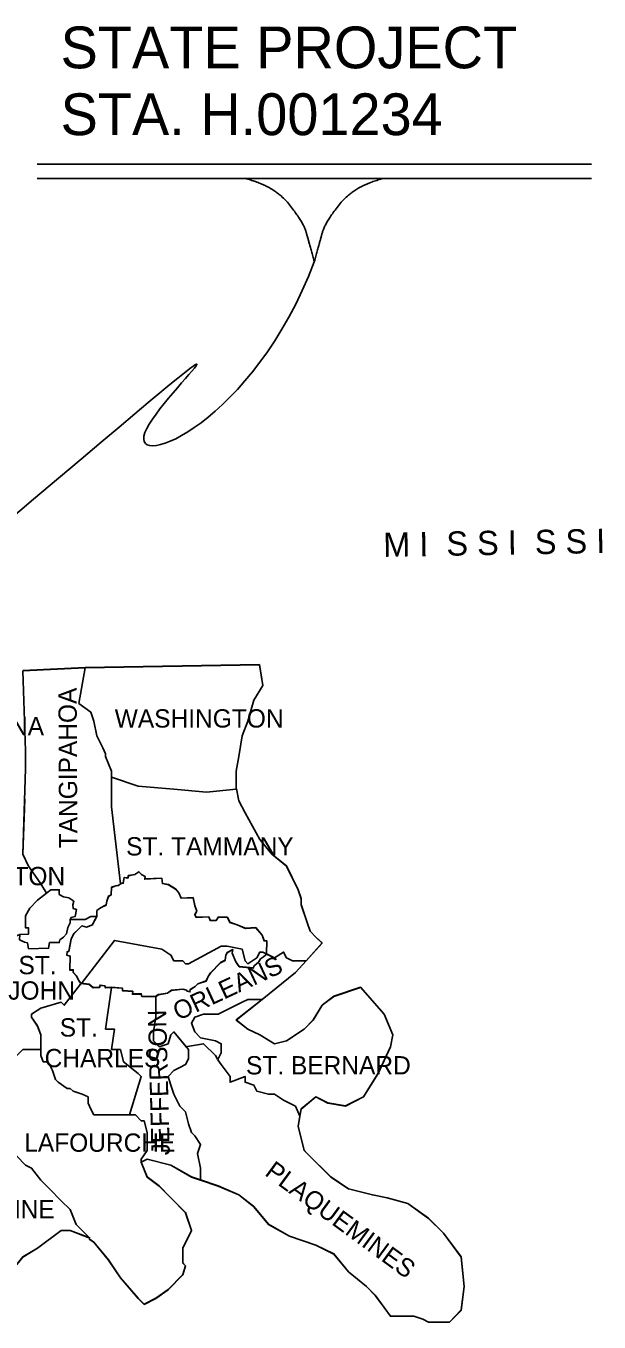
# Model space of a CAD drawing. Extents: x 0.23 to 2.82, y 0.04 to 1.79.
# Drawn here: x 2.468 to 2.6143, y 1.4148 to 1.7459 of the extents above; entities that cross this region are included whole.
import ezdxf

# ---------------------------------------------------------------- set-up
doc = ezdxf.new("R2010")
doc.units = 0
for name, color, linetype in [('Annotation', 7, 'Continuous'), ('Dist02', 7, 'Continuous'), ('Dist62', 7, 'Continuous'), ('Standard Info', 7, 'Continuous')]:
    doc.layers.add(name, color=color, linetype=linetype)

msp = doc.modelspace()

# ---------------------------------------------------------------- linework, layer by layer
at = {"layer": 'Annotation'}
for p, q in [((2.47085, 1.7106), (2.6123, 1.7106)), ((2.47085, 1.7069), (2.6123, 1.7069)), ((2.52387, 1.7069), (2.55928, 1.7069))]:
    msp.add_line(p, q, dxfattribs=at)
for points, degree in [([(2.54158, 1.68565), (2.54013, 1.69098), (2.53877, 1.69574), (2.53134, 1.70508), (2.52387, 1.7069)], 2), ([(2.55928, 1.7069), (2.55181, 1.70508), (2.54438, 1.69574), (2.54302, 1.69098), (2.54158, 1.68565)], 2), ([(2.54158, 1.68565), (2.52602, 1.64446), (2.46291, 1.61901), (2.54158, 1.68565), (2.46291, 1.61901)], 3)]:
    msp.add_open_spline(points, degree=degree, dxfattribs=at)
at = {"layer": 'Dist02'}
for points in [[(2.5294, 1.50908), (2.52924, 1.50867), (2.52865, 1.50808), (2.52782, 1.50758), (2.5274, 1.50692), (2.52615, 1.50575), (2.52607, 1.50533), (2.5224, 1.50567), (2.52157, 1.50683), (2.52065, 1.50908), (2.52074, 1.51), (2.51932, 1.50925), (2.51899, 1.50858), (2.51882, 1.50725), (2.51765, 1.50667), (2.51507, 1.504), (2.51449, 1.50308), (2.51399, 1.502), (2.51182, 1.50125), (2.51115, 1.5005), (2.5099, 1.49975), (2.50982, 1.49925), (2.50915, 1.49933), (2.50899, 1.49958), (2.50799, 1.49983), (2.50515, 1.49958), (2.50407, 1.49883), (2.50182, 1.4985), (2.50115, 1.49808)], [(2.53949, 1.50708), (2.53599, 1.50708), (2.53449, 1.50783), (2.53374, 1.50933), (2.5314, 1.50783), (2.5294, 1.50892)], [(2.53674, 1.50408), (2.53949, 1.50708)], [(2.52824, 1.49725), (2.53674, 1.50408)], [(2.4819, 1.50117), (2.47774, 1.49575), (2.47699, 1.4965), (2.47174, 1.495), (2.4694, 1.4935), (2.4694, 1.49275), (2.4709, 1.4905), (2.47174, 1.48817), (2.47174, 1.48442)], [(2.48982, 1.50033), (2.48824, 1.50025), (2.48807, 1.50075), (2.4869, 1.50092), (2.48674, 1.50033), (2.48515, 1.50025), (2.48407, 1.50117), (2.48199, 1.50142)], [(2.50115, 1.49808), (2.49757, 1.498), (2.4974, 1.49867), (2.49515, 1.49867), (2.49524, 1.49933), (2.49265, 1.4995), (2.49265, 1.50008), (2.48982, 1.50033)], [(2.5379, 1.4675), (2.53824, 1.46933), (2.54199, 1.47233), (2.54507, 1.47083), (2.54957, 1.47008), (2.55415, 1.47233), (2.5579, 1.47842), (2.56099, 1.48517), (2.56165, 1.48817), (2.5594, 1.4935), (2.5534, 1.50033), (2.54657, 1.49808), (2.54357, 1.49575), (2.54132, 1.492), (2.53899, 1.48967), (2.53449, 1.48667), (2.5314, 1.48592), (2.52765, 1.48817), (2.52465, 1.48967), (2.52165, 1.492), (2.52824, 1.49725)], [(2.47174, 1.48442), (2.46715, 1.48442), (2.46565, 1.48292), (2.4649, 1.48442), (2.4634, 1.48442), (2.46182, 1.48367), (2.45882, 1.48292), (2.45732, 1.48442), (2.45582, 1.48517), (2.45357, 1.48517), (2.44599, 1.48517), (2.44599, 1.48367), (2.44299, 1.48067), (2.44215, 1.47908), (2.44215, 1.47683), (2.44065, 1.47458), (2.4384, 1.47083), (2.4369, 1.4685)], [(2.51257, 1.45117), (2.51707, 1.44967), (2.52232, 1.44733), (2.52615, 1.44433), (2.5299, 1.43983), (2.53524, 1.43675), (2.54199, 1.4345), (2.54657, 1.43225), (2.55032, 1.42767), (2.5549, 1.42392), (2.55715, 1.42167), (2.5594, 1.41858), (2.56099, 1.41633), (2.56315, 1.41633), (2.56549, 1.41633), (2.56699, 1.41633), (2.56924, 1.41558), (2.57074, 1.41483), (2.57607, 1.41483), (2.57907, 1.41792), (2.57982, 1.42392), (2.57907, 1.4315), (2.57457, 1.43758), (2.57074, 1.44133), (2.56549, 1.44508), (2.56015, 1.44658), (2.5564, 1.44733), (2.55032, 1.44883), (2.54582, 1.45192), (2.53974, 1.45792), (2.53899, 1.45875), (2.53749, 1.46475), (2.5379, 1.46742)], [(2.48407, 1.43608), (2.48532, 1.43525), (2.48907, 1.43075), (2.49207, 1.42617), (2.49665, 1.42092), (2.49815, 1.41942), (2.50115, 1.42092), (2.50424, 1.42317), (2.50799, 1.427), (2.50874, 1.42917), (2.50799, 1.43), (2.50799, 1.43375), (2.51024, 1.43825), (2.50874, 1.44283), (2.50499, 1.44658), (2.50199, 1.44967), (2.4989, 1.45192), (2.4974, 1.45567)], [(2.4974, 1.45567), (2.4989, 1.45642), (2.50499, 1.45492), (2.51024, 1.45192), (2.51257, 1.45117)], [(2.41574, 1.43492), (2.41799, 1.43225), (2.42782, 1.4285), (2.43465, 1.42617), (2.44449, 1.42167), (2.44749, 1.42167), (2.45432, 1.42242), (2.45582, 1.42317), (2.46115, 1.42542), (2.46415, 1.42767), (2.46715, 1.4315), (2.4709, 1.43375), (2.47699, 1.43825), (2.47924, 1.43825), (2.48424, 1.43633)]]:
    msp.add_lwpolyline(points, dxfattribs=at)
at = {"layer": 'Dist62'}
for p, q in [((2.48307, 1.582), (2.52757, 1.58275)), ((2.46715, 1.58125), (2.48307, 1.582))]:
    msp.add_line(p, q, dxfattribs=at)
for points in [[(2.52757, 1.58275), (2.5284, 1.57742), (2.52615, 1.57367), (2.52465, 1.56833), (2.52315, 1.56458), (2.52232, 1.55925), (2.52165, 1.5555), (2.52165, 1.551)], [(2.52174, 1.551), (2.52232, 1.548), (2.5239, 1.54492), (2.52765, 1.53808), (2.53074, 1.53433), (2.53449, 1.53133), (2.53749, 1.52525), (2.53824, 1.523), (2.53824, 1.5215), (2.53974, 1.51692), (2.54049, 1.51467), (2.54199, 1.51317), (2.54357, 1.51167), (2.53949, 1.50708)], [(2.5294, 1.50908), (2.52949, 1.51217), (2.52874, 1.51225), (2.52824, 1.51367), (2.52665, 1.51558), (2.52399, 1.51542), (2.5219, 1.51625), (2.51999, 1.517), (2.5194, 1.51825), (2.51715, 1.51833), (2.51657, 1.51742), (2.51499, 1.5175), (2.51465, 1.51833), (2.5114, 1.51825), (2.51107, 1.51892), (2.51157, 1.51975), (2.51107, 1.52125), (2.51065, 1.52325), (2.50757, 1.52308), (2.50699, 1.5245), (2.50615, 1.5255), (2.5044, 1.52658), (2.50282, 1.52683), (2.50265, 1.52817), (2.49832, 1.528), (2.4984, 1.52867), (2.49749, 1.52917), (2.49682, 1.52983), (2.49574, 1.52917), (2.49415, 1.52892), (2.49399, 1.52833), (2.49307, 1.52842), (2.49282, 1.527), (2.49207, 1.52675)], [(2.49207, 1.52675), (2.49165, 1.52642), (2.4909, 1.52625), (2.48982, 1.52592), (2.48974, 1.52392), (2.48907, 1.52358), (2.48865, 1.52233), (2.48849, 1.52142), (2.48699, 1.52067), (2.48607, 1.51992), (2.48607, 1.51842)], [(2.48607, 1.51842), (2.48549, 1.51742), (2.48499, 1.51633), (2.4834, 1.51567), (2.48224, 1.516), (2.48149, 1.51525), (2.48024, 1.51408), (2.47949, 1.51275), (2.4789, 1.50958), (2.47849, 1.50942), (2.4784, 1.50858), (2.47924, 1.50833), (2.47915, 1.50483), (2.48007, 1.50483), (2.48007, 1.50417), (2.4809, 1.50325), (2.48149, 1.50208), (2.48199, 1.50142)], [(2.53949, 1.50708), (2.53599, 1.50708), (2.53449, 1.50783), (2.53374, 1.50933), (2.5314, 1.50783), (2.5294, 1.50892)], [(2.4819, 1.50117), (2.47774, 1.49575), (2.47699, 1.4965), (2.47174, 1.495), (2.4694, 1.4935), (2.4694, 1.49275), (2.4709, 1.4905), (2.47174, 1.48817), (2.47174, 1.48442)], [(2.47174, 1.48442), (2.46715, 1.48442), (2.46565, 1.48292), (2.4649, 1.48442), (2.4634, 1.48442), (2.46182, 1.48367), (2.46115, 1.4835)]]:
    msp.add_lwpolyline(points, dxfattribs=at)
at = {"layer": 'Standard Info'}
for p, q in [((2.48307, 1.58192), (2.52757, 1.58267)), ((2.46715, 1.58117), (2.48307, 1.58192)), ((2.52165, 1.55092), (2.52174, 1.551)), ((2.50882, 1.48517), (2.50874, 1.48517)), ((2.51699, 1.48183), (2.51707, 1.48208))]:
    msp.add_line(p, q, dxfattribs=at)
for points in [[(2.52757, 1.58267), (2.5284, 1.57742), (2.52615, 1.57367), (2.52465, 1.56833), (2.52315, 1.56458), (2.52232, 1.55925), (2.52165, 1.5555), (2.52165, 1.55092)], [(2.47324, 1.52442), (2.47324, 1.52442), (2.47174, 1.52675), (2.47024, 1.529), (2.46865, 1.53125), (2.46715, 1.53433), (2.4679, 1.55625), (2.4679, 1.56075), (2.46715, 1.58117)], [(2.48307, 1.58192), (2.48149, 1.57283), (2.48457, 1.57058), (2.48532, 1.56833), (2.48607, 1.56458), (2.48757, 1.5615), (2.48832, 1.56), (2.48832, 1.55925), (2.48982, 1.5555), (2.48982, 1.54642), (2.49207, 1.52675)], [(2.48982, 1.554), (2.48982, 1.5555), (2.48832, 1.55925), (2.48832, 1.56), (2.48757, 1.5615), (2.48607, 1.56458), (2.48532, 1.56833), (2.48457, 1.57058), (2.48149, 1.57283), (2.48307, 1.58192)], [(2.52165, 1.55092), (2.51407, 1.55017), (2.50574, 1.55092), (2.49665, 1.55167), (2.48982, 1.554)], [(2.49207, 1.52675), (2.48982, 1.54642), (2.48982, 1.554)], [(2.48982, 1.554), (2.49665, 1.55167), (2.50574, 1.55092), (2.51407, 1.55017), (2.52165, 1.55092)], [(2.52174, 1.551), (2.52232, 1.54792), (2.5239, 1.54492), (2.52765, 1.53808), (2.53074, 1.53433), (2.53449, 1.53125), (2.53749, 1.52525), (2.53824, 1.52292), (2.53824, 1.52142), (2.53974, 1.51692), (2.54049, 1.51467), (2.54199, 1.51317), (2.54357, 1.51158), (2.53949, 1.50708)], [(2.46765, 1.54842), (2.46715, 1.53433), (2.46865, 1.53125), (2.47024, 1.529), (2.47174, 1.52675), (2.47324, 1.52442)], [(2.5294, 1.509), (2.52949, 1.51208), (2.52874, 1.51217), (2.52824, 1.51367), (2.52665, 1.5155), (2.52399, 1.51533), (2.5219, 1.51625), (2.51999, 1.51692), (2.5194, 1.51817), (2.51715, 1.51825), (2.51657, 1.51742), (2.51499, 1.51742), (2.51465, 1.51833), (2.5114, 1.51817), (2.51107, 1.51883), (2.51157, 1.51975), (2.51107, 1.52117), (2.51065, 1.52317), (2.50757, 1.52308), (2.50699, 1.5245), (2.50615, 1.52542), (2.5044, 1.5265), (2.50282, 1.52683), (2.50265, 1.52817), (2.49832, 1.52792), (2.4984, 1.52867), (2.49749, 1.52917), (2.49682, 1.52983), (2.49574, 1.52917), (2.49415, 1.52883), (2.49399, 1.52825), (2.49307, 1.52842), (2.49282, 1.52692), (2.49207, 1.52675)], [(2.49207, 1.52675), (2.49165, 1.52633), (2.4909, 1.52625), (2.48982, 1.52583), (2.48974, 1.52392), (2.48907, 1.5235), (2.48865, 1.52233), (2.48849, 1.52133), (2.48699, 1.52067), (2.48607, 1.51992), (2.48607, 1.51842)], [(2.47324, 1.52442), (2.4709, 1.52258), (2.46899, 1.52058), (2.46782, 1.51858), (2.4679, 1.5155), (2.46865, 1.5155), (2.46865, 1.51392), (2.4664, 1.51383), (2.46265, 1.51233)], [(2.47924, 1.51767), (2.47949, 1.51817), (2.48057, 1.51842), (2.4809, 1.52017), (2.48007, 1.52042), (2.4799, 1.52142), (2.48024, 1.52233), (2.4789, 1.52317), (2.47757, 1.52342), (2.47649, 1.52408), (2.47649, 1.52525), (2.47432, 1.52525), (2.47324, 1.52442)], [(2.4664, 1.51383), (2.46632, 1.5125), (2.46757, 1.51183), (2.4684, 1.51167), (2.46865, 1.51017), (2.47374, 1.51033), (2.47399, 1.51175), (2.47649, 1.51175), (2.47665, 1.51242), (2.47757, 1.51317), (2.47832, 1.514), (2.47865, 1.51558), (2.47924, 1.51683), (2.47924, 1.51767)], [(2.48607, 1.51842), (2.48549, 1.51733), (2.48499, 1.51625), (2.4834, 1.51567), (2.48224, 1.516), (2.48149, 1.51525), (2.48024, 1.514), (2.47949, 1.51267), (2.4789, 1.5095), (2.47849, 1.50942), (2.4784, 1.50858), (2.47924, 1.50833), (2.47915, 1.50475), (2.48007, 1.50475), (2.48007, 1.50408), (2.4809, 1.50317), (2.48149, 1.502), (2.48199, 1.50133)], [(2.48607, 1.51842), (2.48457, 1.51842), (2.48307, 1.51767), (2.47924, 1.51767)], [(2.47924, 1.51767), (2.48307, 1.51767), (2.48457, 1.51842), (2.48607, 1.51842)], [(2.48207, 1.50125), (2.49057, 1.51233), (2.50265, 1.51008), (2.50499, 1.50858), (2.50574, 1.50708), (2.50799, 1.50708), (2.50874, 1.50633), (2.50949, 1.50633), (2.51782, 1.51083), (2.51932, 1.51083), (2.52315, 1.51008), (2.5239, 1.50708), (2.52465, 1.50633), (2.5269, 1.50783), (2.52765, 1.50933), (2.5284, 1.50933), (2.52932, 1.50892)], [(2.48207, 1.50125), (2.49057, 1.51233), (2.50265, 1.51008), (2.50499, 1.50858), (2.50574, 1.50708), (2.50799, 1.50708), (2.50874, 1.50633), (2.50949, 1.50633), (2.51782, 1.51083), (2.51932, 1.51083), (2.52315, 1.51008), (2.5239, 1.50708), (2.52465, 1.50633), (2.5269, 1.50783), (2.52765, 1.50933), (2.5284, 1.50933), (2.52932, 1.50892)], [(2.50115, 1.498), (2.50182, 1.49842), (2.50407, 1.49883), (2.50515, 1.4995), (2.50799, 1.49983), (2.50899, 1.49958), (2.50915, 1.49933), (2.50982, 1.49917), (2.5099, 1.49967), (2.51115, 1.5005), (2.51182, 1.50125), (2.51399, 1.50192), (2.51449, 1.50308), (2.51507, 1.50392), (2.51765, 1.50658), (2.51882, 1.50717), (2.51899, 1.50858), (2.51932, 1.50917), (2.52074, 1.51), (2.52065, 1.50908), (2.52157, 1.50683), (2.5224, 1.50558), (2.52607, 1.50525), (2.52615, 1.50575), (2.5274, 1.50683), (2.52782, 1.50758), (2.52865, 1.50808), (2.52924, 1.50867), (2.5294, 1.509)], [(2.5294, 1.50883), (2.5314, 1.50783), (2.53374, 1.50933), (2.53449, 1.50783), (2.53599, 1.50708), (2.53949, 1.50708)], [(2.53899, 1.50708), (2.53599, 1.50708), (2.53449, 1.50783), (2.53374, 1.50933), (2.5314, 1.50783), (2.5294, 1.50883)], [(2.53949, 1.50708), (2.53674, 1.50408)], [(2.53674, 1.50408), (2.52824, 1.49725)], [(2.4819, 1.50117), (2.47774, 1.49575), (2.47699, 1.4965), (2.47174, 1.495), (2.4694, 1.4935), (2.4694, 1.49267), (2.4709, 1.49042), (2.47174, 1.48817), (2.47174, 1.48442)], [(2.47174, 1.48442), (2.47174, 1.48817), (2.4709, 1.49042), (2.4694, 1.49267), (2.4694, 1.4935), (2.47174, 1.495), (2.47699, 1.4965), (2.47774, 1.49575), (2.4819, 1.50117)], [(2.48199, 1.50133), (2.48407, 1.50108), (2.48515, 1.50017), (2.48674, 1.50025), (2.4869, 1.50083), (2.48807, 1.50075), (2.48824, 1.50017), (2.48982, 1.50025)], [(2.48982, 1.50025), (2.48832, 1.48967), (2.49057, 1.48967), (2.48982, 1.48442), (2.49207, 1.48442), (2.4929, 1.48133), (2.49665, 1.47833), (2.4974, 1.47758), (2.4944, 1.46775)], [(2.4944, 1.46775), (2.4974, 1.47758), (2.49665, 1.47833), (2.4929, 1.48133), (2.49207, 1.48442), (2.48982, 1.48442), (2.49057, 1.48967), (2.48832, 1.48967), (2.48982, 1.50025)], [(2.48982, 1.50025), (2.49265, 1.50008), (2.49265, 1.49942), (2.49524, 1.49925), (2.49515, 1.49858), (2.4974, 1.49858), (2.49757, 1.498), (2.50115, 1.498)], [(2.52824, 1.49725), (2.52165, 1.49192), (2.52465, 1.48967), (2.52765, 1.48817), (2.5314, 1.48592), (2.53449, 1.48667), (2.53899, 1.48967), (2.54132, 1.49192), (2.54357, 1.49575), (2.54657, 1.498), (2.5534, 1.50025), (2.5594, 1.4935), (2.56165, 1.48817), (2.56099, 1.48517), (2.5579, 1.47833), (2.55415, 1.47233), (2.54957, 1.47), (2.54507, 1.47075), (2.54199, 1.47233), (2.53824, 1.46925), (2.5379, 1.46742)], [(2.50115, 1.498), (2.50115, 1.49267), (2.50049, 1.48892), (2.50049, 1.48667), (2.50199, 1.48517), (2.50424, 1.48592), (2.50499, 1.48817), (2.50574, 1.48892), (2.50949, 1.48442), (2.50949, 1.48208), (2.50874, 1.48058), (2.50724, 1.47983), (2.50574, 1.47908), (2.50424, 1.47758), (2.50499, 1.47533), (2.50574, 1.473), (2.50724, 1.47), (2.50874, 1.4685), (2.50949, 1.4655), (2.51024, 1.46325), (2.51107, 1.46242), (2.51257, 1.46017), (2.51174, 1.45792), (2.51257, 1.45417), (2.51257, 1.45108)], [(2.5089, 1.48517), (2.50574, 1.48892), (2.50499, 1.48817), (2.50424, 1.48592), (2.50199, 1.48517), (2.50049, 1.48667), (2.50049, 1.48892), (2.50115, 1.49267), (2.50115, 1.498)], [(2.52824, 1.49725), (2.52615, 1.49725), (2.52465, 1.49725), (2.52315, 1.4965), (2.52007, 1.495), (2.51707, 1.4935), (2.51332, 1.4935), (2.51107, 1.49267), (2.51024, 1.49117), (2.51107, 1.48892), (2.51257, 1.48742), (2.51632, 1.48667), (2.51782, 1.48592), (2.51782, 1.48358), (2.51707, 1.48208)], [(2.51707, 1.48208), (2.51782, 1.48358), (2.51782, 1.48592), (2.51632, 1.48667), (2.51257, 1.48742), (2.51107, 1.48892), (2.51024, 1.49117), (2.51107, 1.49267), (2.51332, 1.4935), (2.51707, 1.4935), (2.52007, 1.495), (2.52315, 1.4965), (2.52465, 1.49725), (2.52615, 1.49725), (2.52824, 1.49725)], [(2.4369, 1.4685), (2.4384, 1.47075), (2.44065, 1.4745), (2.44215, 1.47683), (2.44215, 1.47908), (2.44299, 1.48058), (2.44599, 1.48358), (2.44599, 1.48517), (2.45357, 1.48517), (2.45582, 1.48517), (2.45732, 1.48442), (2.45882, 1.48292), (2.46182, 1.48358), (2.4634, 1.48442), (2.4649, 1.48442), (2.46565, 1.48292), (2.46715, 1.48442), (2.47174, 1.48442)], [(2.47174, 1.48442), (2.46715, 1.48442), (2.46565, 1.48292), (2.4649, 1.48442), (2.4634, 1.48442), (2.46182, 1.48358), (2.46115, 1.48342)], [(2.47174, 1.48442), (2.47174, 1.48292), (2.4724, 1.48133), (2.47324, 1.48133), (2.47399, 1.48058), (2.47474, 1.47908), (2.47549, 1.47683), (2.47624, 1.47608), (2.47849, 1.4745), (2.47924, 1.4745), (2.47999, 1.47383), (2.48232, 1.473), (2.48382, 1.47233), (2.48382, 1.47075), (2.48457, 1.46925), (2.48532, 1.46775), (2.4959, 1.46775), (2.4974, 1.46625), (2.49815, 1.46625), (2.4989, 1.46325), (2.4989, 1.46092), (2.4989, 1.45867), (2.4974, 1.45642), (2.4974, 1.45567)], [(2.4944, 1.46775), (2.48532, 1.46775), (2.48457, 1.46925), (2.48382, 1.47075), (2.48382, 1.47233), (2.48232, 1.473), (2.47999, 1.47383), (2.47924, 1.4745), (2.47849, 1.4745), (2.47624, 1.47608), (2.47549, 1.47683), (2.47474, 1.47908), (2.47399, 1.48058), (2.47324, 1.48133), (2.4724, 1.48133), (2.47174, 1.48292), (2.47174, 1.48442)], [(2.51257, 1.45108), (2.51257, 1.45417), (2.51174, 1.45792), (2.51257, 1.46017), (2.51107, 1.46242), (2.51024, 1.46325), (2.50949, 1.4655), (2.50874, 1.4685), (2.50724, 1.47), (2.50574, 1.473), (2.50499, 1.47533), (2.50424, 1.47758), (2.50574, 1.47908), (2.50724, 1.47983), (2.50874, 1.48058), (2.50949, 1.48208), (2.50949, 1.48442), (2.50882, 1.48517)], [(2.5169, 1.482), (2.51632, 1.48292), (2.51332, 1.48592), (2.50874, 1.48517)], [(2.50874, 1.48517), (2.51332, 1.48592), (2.51632, 1.48292), (2.5169, 1.482)], [(2.5379, 1.46742), (2.53674, 1.47), (2.53374, 1.4715), (2.5314, 1.473), (2.5299, 1.473), (2.5269, 1.47383), (2.52615, 1.47533), (2.5239, 1.47608), (2.5239, 1.47758), (2.52007, 1.47608), (2.52007, 1.47758), (2.51782, 1.48058), (2.51699, 1.48183)], [(2.51699, 1.48183), (2.51782, 1.48058), (2.52007, 1.47758), (2.52007, 1.47608), (2.5239, 1.47758), (2.5239, 1.47608), (2.52615, 1.47533), (2.5269, 1.47383), (2.5299, 1.473), (2.5314, 1.473), (2.53374, 1.4715), (2.53674, 1.47), (2.5379, 1.46742)], [(2.4369, 1.4685), (2.44599, 1.4685), (2.44599, 1.47075), (2.44899, 1.4715), (2.45057, 1.473), (2.45282, 1.4715), (2.45357, 1.47), (2.45507, 1.467), (2.45657, 1.46392), (2.46032, 1.46325), (2.46415, 1.46092), (2.4634, 1.45867), (2.46565, 1.45717), (2.4679, 1.45492), (2.4694, 1.45417), (2.47174, 1.45108), (2.47399, 1.44883), (2.47699, 1.44583), (2.47924, 1.44358), (2.48082, 1.43975), (2.48424, 1.43625)], [(2.48424, 1.43625), (2.48082, 1.43975), (2.47924, 1.44358), (2.47699, 1.44583), (2.47399, 1.44883), (2.47174, 1.45108), (2.4694, 1.45417), (2.4679, 1.45492), (2.46565, 1.45717), (2.4634, 1.45867), (2.46415, 1.46092), (2.46032, 1.46325), (2.45657, 1.46392), (2.45507, 1.467), (2.45357, 1.47), (2.45282, 1.4715), (2.45057, 1.473), (2.44899, 1.4715), (2.44599, 1.47075), (2.44599, 1.4685), (2.4369, 1.4685)], [(2.4974, 1.45567), (2.4974, 1.45642), (2.4989, 1.45867), (2.4989, 1.46092), (2.4989, 1.46325), (2.49815, 1.46625), (2.4974, 1.46625), (2.4959, 1.46775), (2.4944, 1.46775)], [(2.5379, 1.46742), (2.53749, 1.46475), (2.53899, 1.45867), (2.53974, 1.45792), (2.54582, 1.45183), (2.55032, 1.44883), (2.5564, 1.44733), (2.56015, 1.44658), (2.56549, 1.44508), (2.57074, 1.44125), (2.57457, 1.4375), (2.57907, 1.43142), (2.57982, 1.42392), (2.57907, 1.41783), (2.57607, 1.41483), (2.57074, 1.41483), (2.56924, 1.41558), (2.56699, 1.41633), (2.56549, 1.41633), (2.56315, 1.41633), (2.56099, 1.41633), (2.5594, 1.41858), (2.55715, 1.42158), (2.5549, 1.42392), (2.55032, 1.42767), (2.54657, 1.43217), (2.54199, 1.4345), (2.53524, 1.43675), (2.5299, 1.43975), (2.52615, 1.44425), (2.52232, 1.44733), (2.51707, 1.44958), (2.51257, 1.45108)], [(2.4974, 1.45567), (2.4989, 1.45183), (2.50199, 1.44958), (2.50499, 1.44658), (2.50874, 1.44275), (2.51024, 1.43825), (2.50799, 1.43367), (2.50799, 1.42992), (2.50874, 1.42917), (2.50799, 1.42692), (2.50424, 1.42308), (2.50115, 1.42083), (2.49815, 1.41933), (2.49665, 1.42083), (2.49207, 1.42617), (2.48907, 1.43067), (2.48532, 1.43525), (2.48407, 1.436)], [(2.51257, 1.45108), (2.51024, 1.45183), (2.50499, 1.45492), (2.4989, 1.45642), (2.4974, 1.45567)], [(2.48424, 1.43625), (2.47924, 1.43825), (2.47699, 1.43825), (2.4709, 1.43367), (2.46715, 1.43142), (2.46415, 1.42767), (2.46115, 1.42542), (2.45582, 1.42308), (2.45432, 1.42242), (2.44749, 1.42158), (2.44449, 1.42158), (2.43465, 1.42617), (2.42782, 1.42842), (2.41799, 1.43217), (2.41574, 1.43492)]]:
    msp.add_lwpolyline(points, dxfattribs=at)

# ---------------------------------------------------------------- texts
for s, height, p in [('STATE PROJECT', 0.01067, (2.47681, 1.73505)), ('STA. H.001234', 0.01067, (2.47681, 1.71798)), ('HELENA', 0.004679, (2.44756, 1.56469)), ('WASHINGTON', 0.004679, (2.49063, 1.56667)), ('ST. TAMMANY', 0.004679, (2.49354, 1.534)), ('LIVINGSTON', 0.004679, (2.44009, 1.5264)), ('ST.', 0.004679, (2.46607, 1.50367)), ('JOHN', 0.004679, (2.46345, 1.49718)), ('ST.', 0.004679, (2.4766, 1.48775)), ('CHARLES', 0.004679, (2.47275, 1.47992)), ('ST. BERNARD', 0.004679, (2.52414, 1.47808)), ('LAFOURCHE', 0.004679, (2.46753, 1.45833)), ('TERREBONNE', 0.004679, (2.43184, 1.44133))]:
    msp.add_text(s, height=height, dxfattribs=at).set_placement(p)
for s, height, rotation, p in [('M I  S S I  S S I  P P I', 0.0062, 1.0059, (2.55922, 1.61026)), ('TANGIPAHOA', 0.004679, 90.2537, (2.48111, 1.53585)), ('ORLEANS', 0.004678, 24.9246, (2.50686, 1.49175)), ('JEFFERSON', 0.004679, 91.4837, (2.50471, 1.45746)), ('PLAQUEMINES', 0.004679, 323.7253, (2.52868, 1.45249))]:
    msp.add_text(s, height=height, rotation=rotation, dxfattribs=at).set_placement(p)

doc.saveas('drawing.dxf')
